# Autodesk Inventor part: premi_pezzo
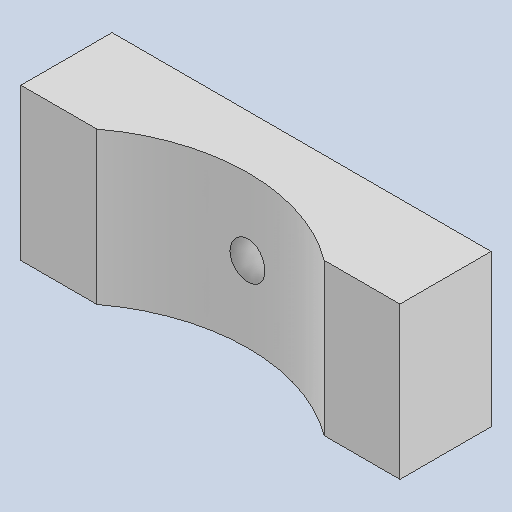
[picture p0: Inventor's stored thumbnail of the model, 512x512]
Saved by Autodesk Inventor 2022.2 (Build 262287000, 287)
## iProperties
Created: 2024-10
Part Number: premi_pezzo
Material: Generico
Document SubType Name: Modeling
Designer: 18907419
Density: 1 g/cm^3
Appearance: Default
Author: 18907419
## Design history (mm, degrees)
feature "Solido1"
node "Solido2"
